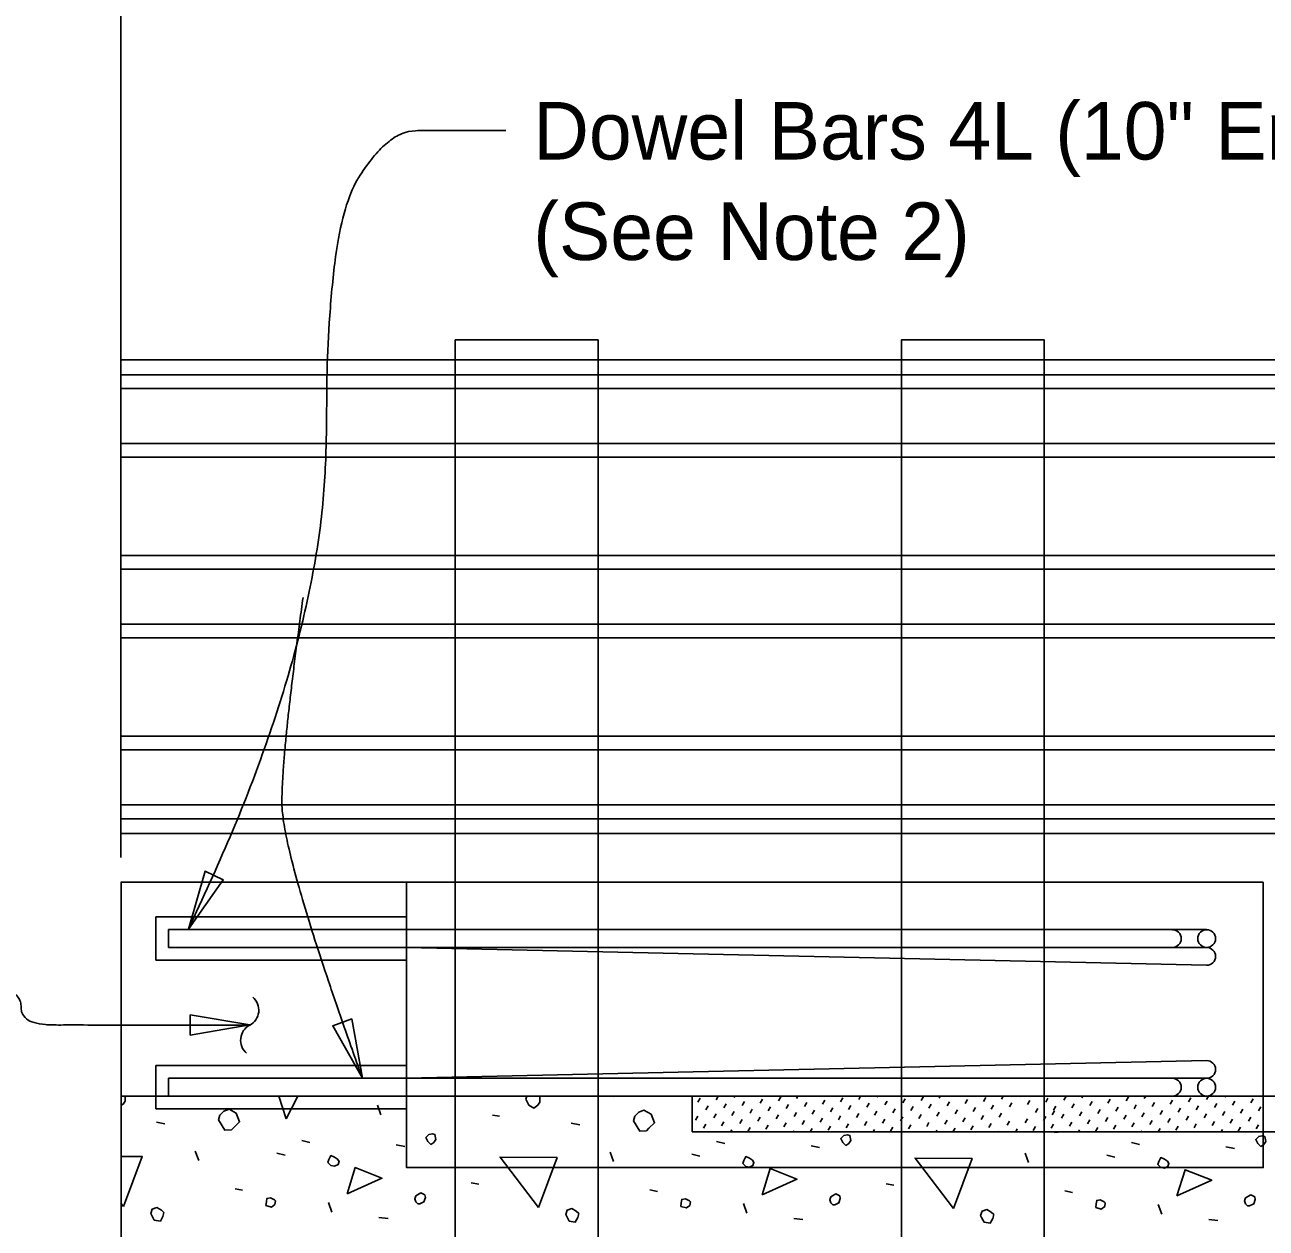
# Model space of a CAD drawing. Extents: x 0 to 41.1, y 0 to 26.
# Drawn here: x 5.42 to 9.767, y 10.482 to 14.698 of the extents above; entities that cross this region are included whole.
import ezdxf

# ---------------------------------------------------------------- set-up
doc = ezdxf.new("R2010")
doc.units = 0
for name, color, linetype in [('Dimension', 7, 'Continuous'), ('Miscellaneous', 7, 'Continuous'), ('Rebar', 7, 'Continuous'), ('TrafBarrierConc', 7, 'Continuous')]:
    doc.layers.add(name, color=color, linetype=linetype)

msp = doc.modelspace()

# ---------------------------------------------------------------- linework, layer by layer
at = {"layer": 'Dimension'}
for points in [[(5.9925, 11.5299), (6.1145, 11.7023), (6.051, 11.7329)], [(6.2076, 11.194), (5.9993, 11.2292), (5.9993, 11.1587)], [(6.6021, 11.0071), (6.5646, 11.215), (6.4983, 11.1911)]]:
    msp.add_lwpolyline(points, close=True, dxfattribs=at)
for centre, start, end in [((6.1796, 11.246), 297.7814, 49.5086), ((6.2351, 11.1405), 117.7814, 229.5086)]:
    msp.add_arc(centre, 0.0596, start, end, dxfattribs=at)
for points in [[(7.104, 14.328), (6.8988, 14.328), (6.6871, 14.328), (6.4754, 13.9706), (6.4754, 12.5343), (5.9925, 11.5299)], [(6.3942, 12.6913), (6.3201, 12.1537), (6.3201, 11.7897), (6.6021, 11.0071)], [(5.0828, 11.3131), (5.2747, 11.3131), (5.407, 11.3131), (5.407, 11.1939), (5.6386, 11.1939), (6.2076, 11.1939)]]:
    msp.add_open_spline(points, degree=2, dxfattribs=at)
at = {"layer": 'Miscellaneous'}
for p, q in [((5.7566, 19.1069), (5.7566, 11.7803)), ((5.7567, 13.5247), (11.6026, 13.5247)), ((5.7567, 13.4725), (11.6026, 13.4725)), ((5.7567, 13.4242), (11.6026, 13.4242)), ((5.7567, 13.2314), (11.6026, 13.2314)), ((5.7567, 13.1832), (11.6026, 13.1832)), ((5.7567, 12.8392), (11.6026, 12.8392)), ((5.7567, 12.791), (11.6026, 12.791)), ((5.7567, 12.5982), (11.6026, 12.5982)), ((5.7567, 12.5501), (11.6026, 12.5501)), ((5.7567, 12.2061), (11.6026, 12.2061)), ((5.7567, 12.1579), (11.6026, 12.1579)), ((5.7567, 11.9651), (11.6026, 11.9651)), ((5.7567, 11.9168), (11.6026, 11.9168)), ((5.7567, 11.8646), (11.6026, 11.8646)), ((6.667, 10.8797), (6.6546, 10.9133)), ((7.7771, 10.9238), (7.7852, 10.9378)), ((7.8406, 10.9319), (7.848, 10.9447)), ((7.8683, 10.9042), (7.8764, 10.9182)), ((7.9041, 10.94), (7.9068, 10.9447)), ((7.9318, 10.9123), (7.9399, 10.9263)), ((7.9953, 10.9204), (8.0034, 10.9344)), ((8.0588, 10.9285), (8.0669, 10.9425)), ((8.0864, 10.9008), (8.0946, 10.9148)), ((8.1222, 10.9366), (8.1269, 10.9447)), ((8.1499, 10.9089), (8.158, 10.9229)), ((8.2134, 10.917), (8.2215, 10.931)), ((8.2769, 10.9251), (8.285, 10.9391)), ((8.3404, 10.9332), (8.347, 10.9447)), ((8.3681, 10.9055), (8.3762, 10.9195)), ((8.4039, 10.9413), (8.4058, 10.9447)), ((8.4316, 10.9136), (8.4397, 10.9276)), ((8.4951, 10.9217), (8.5032, 10.9357)), ((8.5586, 10.9298), (8.5667, 10.9438)), ((8.5863, 10.9021), (8.5944, 10.9161)), ((8.6221, 10.9379), (8.626, 10.9447)), ((8.6498, 10.9102), (8.6579, 10.9242)), ((8.7133, 10.9183), (8.7214, 10.9323)), ((8.7768, 10.9264), (8.7849, 10.9404)), ((8.8045, 10.8987), (8.8126, 10.9127)), ((8.8403, 10.9345), (8.8461, 10.9447)), ((8.8679, 10.9068), (8.8761, 10.9208)), ((8.9037, 10.9426), (8.9049, 10.9447)), ((8.9314, 10.9149), (8.9395, 10.9289)), ((8.9949, 10.923), (9.003, 10.937)), ((9.0584, 10.9311), (9.0662, 10.9447)), ((9.0861, 10.9035), (9.0942, 10.9174)), ((9.1219, 10.9392), (9.125, 10.9447)), ((9.1496, 10.9116), (9.1577, 10.9255)), ((9.2131, 10.9197), (9.2212, 10.9337)), ((9.2766, 10.9278), (9.2847, 10.9418)), ((9.3043, 10.9001), (9.3124, 10.9141)), ((9.3401, 10.9359), (9.3452, 10.9447)), ((9.3678, 10.9082), (9.3759, 10.9222)), ((9.4036, 10.944), (9.404, 10.9447)), ((9.4313, 10.9163), (9.4394, 10.9303)), ((9.4948, 10.9244), (9.5029, 10.9384)), ((9.5583, 10.9325), (9.5653, 10.9447)), ((9.586, 10.9048), (9.5941, 10.9188)), ((9.6218, 10.9406), (9.6241, 10.9447)), ((9.6494, 10.9129), (9.6576, 10.9269)), ((9.7129, 10.921), (9.721, 10.935)), ((7.0577, 10.8779), (7.0824, 10.8744)), ((7.769, 10.8603), (7.7771, 10.8743)), ((7.8048, 10.8961), (7.8129, 10.9101)), ((7.8325, 10.8684), (7.8406, 10.8824)), ((7.896, 10.8765), (7.9041, 10.8905)), ((7.9595, 10.8846), (7.9676, 10.8986)), ((7.9872, 10.8569), (7.9953, 10.8709)), ((8.023, 10.8927), (8.0311, 10.9067)), ((8.0507, 10.865), (8.0588, 10.879)), ((8.1141, 10.8731), (8.1222, 10.8871)), ((8.1776, 10.8812), (8.1857, 10.8952)), ((8.2411, 10.8893), (8.2492, 10.9033)), ((8.2688, 10.8616), (8.2769, 10.8756)), ((8.3046, 10.8974), (8.3127, 10.9114)), ((8.3323, 10.8697), (8.3404, 10.8837)), ((8.3958, 10.8778), (8.4039, 10.8918)), ((8.4593, 10.8859), (8.4674, 10.8999)), ((8.487, 10.8582), (8.4951, 10.8722)), ((8.5228, 10.894), (8.5309, 10.908)), ((8.5505, 10.8663), (8.5586, 10.8803)), ((8.614, 10.8744), (8.6221, 10.8884)), ((8.6775, 10.8825), (8.6856, 10.8965)), ((8.7052, 10.8548), (8.7133, 10.8688)), ((8.741, 10.8906), (8.7491, 10.9046)), ((8.7687, 10.8629), (8.7768, 10.8769)), ((8.8322, 10.871), (8.8403, 10.885)), ((8.9591, 10.8872), (8.9672, 10.9012)), ((8.9868, 10.8596), (8.9949, 10.8735)), ((9.0181, 10.8791), (9.0262, 10.8931)), ((9.0226, 10.8953), (9.0307, 10.9093)), ((9.0503, 10.8677), (9.0584, 10.8816)), ((9.1138, 10.8758), (9.1219, 10.8898)), ((9.1773, 10.8839), (9.1854, 10.8979)), ((9.205, 10.8562), (9.2131, 10.8702)), ((9.2408, 10.892), (9.2489, 10.906)), ((9.2685, 10.8643), (9.2766, 10.8783)), ((9.332, 10.8724), (9.3401, 10.8864)), ((9.3955, 10.8805), (9.4036, 10.8945)), ((9.459, 10.8886), (9.4671, 10.9026)), ((9.4867, 10.8609), (9.4948, 10.8749)), ((9.5225, 10.8967), (9.5306, 10.9107)), ((9.5502, 10.869), (9.5583, 10.883)), ((9.6137, 10.8771), (9.6218, 10.8911)), ((9.6771, 10.8852), (9.6852, 10.8992)), ((9.7048, 10.8575), (9.7129, 10.8715)), ((9.7406, 10.8933), (9.7487, 10.9073)), ((5.8804, 10.8532), (5.9104, 10.8479)), ((7.3335, 10.8497), (7.3635, 10.8444)), ((7.7967, 10.8326), (7.8048, 10.8466)), ((7.8602, 10.8407), (7.8683, 10.8547)), ((7.8917, 10.8197), (7.896, 10.827)), ((7.9237, 10.8488), (7.9318, 10.8628)), ((7.9514, 10.8211), (7.9595, 10.8351)), ((8.0149, 10.8292), (8.023, 10.8432)), ((8.0783, 10.8373), (8.0864, 10.8513)), ((8.1418, 10.8454), (8.1499, 10.8594)), ((8.1707, 10.8197), (8.1776, 10.8317)), ((8.2053, 10.8535), (8.2134, 10.8675)), ((8.233, 10.8258), (8.2411, 10.8398)), ((8.2965, 10.8339), (8.3046, 10.8479)), ((8.36, 10.842), (8.3681, 10.856)), ((8.3908, 10.8197), (8.3958, 10.8283)), ((8.4235, 10.8501), (8.4316, 10.8641)), ((8.4512, 10.8224), (8.4593, 10.8364)), ((8.5147, 10.8305), (8.5228, 10.8445)), ((8.5782, 10.8386), (8.5863, 10.8526)), ((8.6109, 10.8197), (8.614, 10.8249)), ((8.6417, 10.8467), (8.6498, 10.8607)), ((8.6697, 10.8197), (8.6775, 10.833)), ((8.7329, 10.8271), (8.741, 10.8411)), ((8.7964, 10.8352), (8.8045, 10.8492)), ((8.8598, 10.8433), (8.8679, 10.8573)), ((8.8899, 10.8197), (8.8956, 10.8296)), ((8.9233, 10.8514), (8.9314, 10.8654)), ((8.951, 10.8238), (8.9591, 10.8377)), ((9.0145, 10.8319), (9.0226, 10.8459)), ((9.078, 10.84), (9.0861, 10.854)), ((9.11, 10.8197), (9.1138, 10.8263)), ((9.1415, 10.8481), (9.1496, 10.8621)), ((9.1692, 10.8204), (9.1773, 10.8344)), ((9.2327, 10.8285), (9.2408, 10.8425)), ((9.2962, 10.8366), (9.3043, 10.8506)), ((9.3597, 10.8447), (9.3678, 10.8587)), ((9.3889, 10.8197), (9.3955, 10.831)), ((9.4232, 10.8528), (9.4313, 10.8668)), ((9.4509, 10.8251), (9.459, 10.8391)), ((9.5144, 10.8332), (9.5225, 10.8472)), ((9.5779, 10.8413), (9.586, 10.8553)), ((9.6091, 10.8197), (9.6137, 10.8276)), ((9.6413, 10.8494), (9.6494, 10.8634)), ((9.669, 10.8217), (9.6771, 10.8357)), ((9.7325, 10.8298), (9.7406, 10.8438)), ((6.3895, 10.7896), (6.4178, 10.7825)), ((7.8426, 10.786), (7.8709, 10.779)), ((8.1119, 10.8197), (8.1141, 10.8236)), ((8.332, 10.8197), (8.3323, 10.8202)), ((8.8311, 10.8197), (8.8322, 10.8215)), ((9.2957, 10.7825), (9.324, 10.7754)), ((9.3301, 10.8197), (9.332, 10.8229)), ((6.0288, 10.7188), (6.0165, 10.7524)), ((6.3029, 10.7454), (6.3311, 10.7383)), ((6.72, 10.7737), (6.7501, 10.7683)), ((7.482, 10.7153), (7.4696, 10.7489)), ((7.756, 10.7418), (7.7842, 10.7348)), ((8.1732, 10.7701), (8.2032, 10.7648)), ((8.9351, 10.7118), (8.9227, 10.7454)), ((9.2091, 10.7383), (9.2373, 10.7312)), ((9.6263, 10.7666), (9.6563, 10.7613)), ((6.1561, 10.6199), (6.1826, 10.6146)), ((6.9834, 10.6411), (7.01, 10.6358)), ((7.6092, 10.6163), (7.6358, 10.611)), ((8.4365, 10.6375), (8.4631, 10.6322)), ((9.0623, 10.6128), (9.0889, 10.6075)), ((6.4955, 10.5385), (6.4832, 10.5721)), ((7.9486, 10.535), (7.9363, 10.5686)), ((9.4017, 10.5315), (9.3894, 10.5651)), ((6.6599, 10.5191), (6.6918, 10.5156)), ((8.113, 10.5156), (8.1449, 10.512)), ((9.5662, 10.512), (9.598, 10.5085))]:
    msp.add_line(p, q, dxfattribs=at)
for points in [[(7.4275, 9.7744), (7.4275, 13.5946), (6.9275, 13.5946), (6.9275, 9.7744)], [(8.99, 9.7744), (8.99, 13.5946), (8.49, 13.5946), (8.49, 9.7744)], [(5.7566, 10.9115), (5.7637, 10.9168), (5.7708, 10.9274), (5.7708, 10.9447)], [(6.3347, 10.8656), (6.3092, 10.9447)], [(6.3754, 10.9447), (6.3347, 10.8656)], [(7.1744, 10.9345), (7.185, 10.9133), (7.2026, 10.9027), (7.2168, 10.9133), (7.2239, 10.9239), (7.2239, 10.9447)], [(7.1777, 10.9447), (7.1744, 10.9345)], [(7.4794, 10.9447), (7.4802, 10.9434)], [(7.4802, 10.9434), (7.483, 10.9447)], [(6.0978, 10.862), (6.1208, 10.8249), (6.1438, 10.8267), (6.1526, 10.8355), (6.172, 10.855), (6.1597, 10.885), (6.1349, 10.8992), (6.1172, 10.8921), (6.1031, 10.8779), (6.0978, 10.862)], [(7.5509, 10.8585), (7.5739, 10.8214), (7.5969, 10.8231), (7.6057, 10.832), (7.6251, 10.8514), (7.6128, 10.8815), (7.588, 10.8956), (7.5703, 10.8886), (7.5562, 10.8744), (7.5509, 10.8585)], [(6.8314, 10.786), (6.842, 10.7754), (6.8526, 10.7825), (6.8597, 10.7931), (6.8562, 10.8108), (6.8473, 10.8125), (6.835, 10.8108), (6.8243, 10.8002), (6.8314, 10.786)], [(8.2845, 10.7825), (8.2951, 10.7719), (8.3057, 10.779), (8.3128, 10.7896), (8.3093, 10.8072), (8.3004, 10.809), (8.2881, 10.8072), (8.2774, 10.7966), (8.2845, 10.7825)], [(9.0259, 10.8197), (9.027, 10.8178), (9.05, 10.8196), (9.05, 10.8197)], [(9.7376, 10.779), (9.7482, 10.7683), (9.7588, 10.7754), (9.7659, 10.786), (9.7624, 10.8037), (9.7535, 10.8055), (9.7412, 10.8037), (9.7306, 10.7931), (9.7376, 10.779)], [(5.7566, 10.7336), (5.8309, 10.733), (5.7655, 10.558)], [(6.492, 10.7012), (6.5044, 10.6994), (6.5168, 10.7047), (6.5203, 10.7153), (6.515, 10.7242), (6.5044, 10.7312), (6.492, 10.7365), (6.4849, 10.7224), (6.4814, 10.7118), (6.492, 10.7012)], [(7.2186, 10.5544), (7.0842, 10.7312), (7.284, 10.7295), (7.2186, 10.5544)], [(7.9451, 10.6976), (7.9575, 10.6959), (7.9699, 10.7012), (7.9734, 10.7118), (7.9681, 10.7206), (7.9575, 10.7277), (7.9451, 10.733), (7.938, 10.7188), (7.9345, 10.7082), (7.9451, 10.6976)], [(8.6717, 10.5509), (8.5373, 10.7277), (8.7371, 10.7259), (8.6717, 10.5509)], [(9.3982, 10.6941), (9.4106, 10.6923), (9.423, 10.6976), (9.4265, 10.7082), (9.4212, 10.7171), (9.4106, 10.7242), (9.3982, 10.7295), (9.3911, 10.7153), (9.3876, 10.7047), (9.3982, 10.6941)], [(6.5486, 10.6022), (6.5769, 10.6941), (6.6705, 10.657), (6.5486, 10.6022)], [(8.0017, 10.5986), (8.03, 10.6906), (8.1237, 10.6534), (8.0017, 10.5986)], [(9.4548, 10.5951), (9.4831, 10.687), (9.5768, 10.6499), (9.4548, 10.5951)], [(5.7655, 10.558), (5.7566, 10.5696)], [(6.264, 10.5615), (6.2834, 10.5562), (6.2958, 10.5651), (6.2976, 10.5774), (6.294, 10.581), (6.2799, 10.588), (6.2675, 10.5863), (6.2657, 10.5739), (6.264, 10.5615)], [(6.7961, 10.5668), (6.8031, 10.5668), (6.8173, 10.5739), (6.8226, 10.5898), (6.8208, 10.5986), (6.8067, 10.6057), (6.789, 10.5951), (6.7855, 10.5845), (6.789, 10.5739), (6.7961, 10.5668)], [(7.7171, 10.558), (7.7365, 10.5527), (7.7489, 10.5615), (7.7507, 10.5739), (7.7471, 10.5774), (7.733, 10.5845), (7.7206, 10.5827), (7.7188, 10.5704), (7.7171, 10.558)], [(8.2492, 10.5633), (8.2562, 10.5633), (8.2704, 10.5704), (8.2757, 10.5863), (8.2739, 10.5951), (8.2598, 10.6022), (8.2421, 10.5916), (8.2386, 10.581), (8.2421, 10.5704), (8.2492, 10.5633)], [(9.1702, 10.5544), (9.1896, 10.5491), (9.202, 10.558), (9.2038, 10.5704), (9.2002, 10.5739), (9.1861, 10.581), (9.1737, 10.5792), (9.1719, 10.5668), (9.1702, 10.5544)], [(9.7023, 10.5598), (9.7093, 10.5598), (9.7235, 10.5668), (9.7288, 10.5827), (9.727, 10.5916), (9.7129, 10.5986), (9.6952, 10.588), (9.6917, 10.5774), (9.6952, 10.5668), (9.7023, 10.5598)], [(5.8644, 10.5262), (5.8733, 10.5103), (5.8945, 10.5067), (5.9033, 10.5226), (5.9069, 10.5368), (5.898, 10.5456), (5.8821, 10.5544), (5.8662, 10.5491), (5.8609, 10.5332), (5.8644, 10.5262)], [(7.3176, 10.5226), (7.3264, 10.5067), (7.3476, 10.5032), (7.3564, 10.5191), (7.36, 10.5332), (7.3511, 10.5421), (7.3352, 10.5509), (7.3193, 10.5456), (7.314, 10.5297), (7.3176, 10.5226)], [(8.7707, 10.5191), (8.7795, 10.5032), (8.8007, 10.4996), (8.8095, 10.5156), (8.8131, 10.5297), (8.8042, 10.5385), (8.7883, 10.5474), (8.7724, 10.5421), (8.7671, 10.5262), (8.7707, 10.5191)]]:
    msp.add_lwpolyline(points, dxfattribs=at)
at = {"layer": 'Rebar'}
for p, q in [((5.9233, 11.528), (9.5587, 11.528)), ((5.9233, 11.528), (5.9233, 11.4655)), ((5.9233, 11.4655), (9.5587, 11.4655)), ((9.5587, 11.4031), (6.7566, 11.4655)), ((9.5587, 11.0695), (6.7566, 11.0071)), ((5.9233, 11.0071), (9.5587, 11.0071)), ((5.9233, 11.0071), (5.9233, 10.9446)), ((5.9233, 10.9446), (9.5587, 10.9446))]:
    msp.add_line(p, q, dxfattribs=at)
for centre in [(9.5587, 11.4967), (9.5587, 10.9759)]:
    msp.add_circle(centre, 0.0312, dxfattribs=at)
for centre in [(9.4385, 11.4967), (9.5587, 11.4343), (9.5587, 11.4343), (9.5587, 11.0383), (9.4385, 10.9759)]:
    msp.add_arc(centre, 0.0312, 270, 90, dxfattribs=at)
at = {"layer": 'TrafBarrierConc'}
for p, q in [((5.7566, 11.6946), (6.7566, 11.6946)), ((5.7567, 11.6946), (5.7567, 9.0899)), ((6.7566, 11.6946), (9.7566, 11.6946)), ((6.7566, 10.9446), (6.7566, 11.6946)), ((9.7566, 11.6946), (9.7566, 10.9446)), ((5.8788, 11.5724), (5.8788, 11.421)), ((5.8788, 11.5724), (6.7566, 11.5724)), ((5.8788, 11.421), (6.7566, 11.421)), ((5.8788, 11.0516), (5.8788, 10.9002)), ((5.8788, 11.0516), (6.7566, 11.0516)), ((5.7566, 10.9447), (11.4801, 10.9447)), ((7.7567, 10.9447), (7.7567, 10.8197)), ((5.8788, 10.9002), (6.7566, 10.9002)), ((7.7567, 10.8197), (11.4801, 10.8197))]:
    msp.add_line(p, q, dxfattribs=at)
msp.add_lwpolyline([(9.7566, 10.9446), (9.7566, 10.6946), (6.7566, 10.6946), (6.7566, 10.9446)], dxfattribs=at)

# ---------------------------------------------------------------- texts
at = {"layer": 'Dimension'}
for s, p in [('Dowel Bars 4L (10" Embedment) ', (7.2006, 14.2264)), ('(See Note 2)', (7.2006, 13.8744))]:
    msp.add_text(s, height=0.2016, dxfattribs=at).set_placement(p)

doc.saveas('drawing.dxf')
